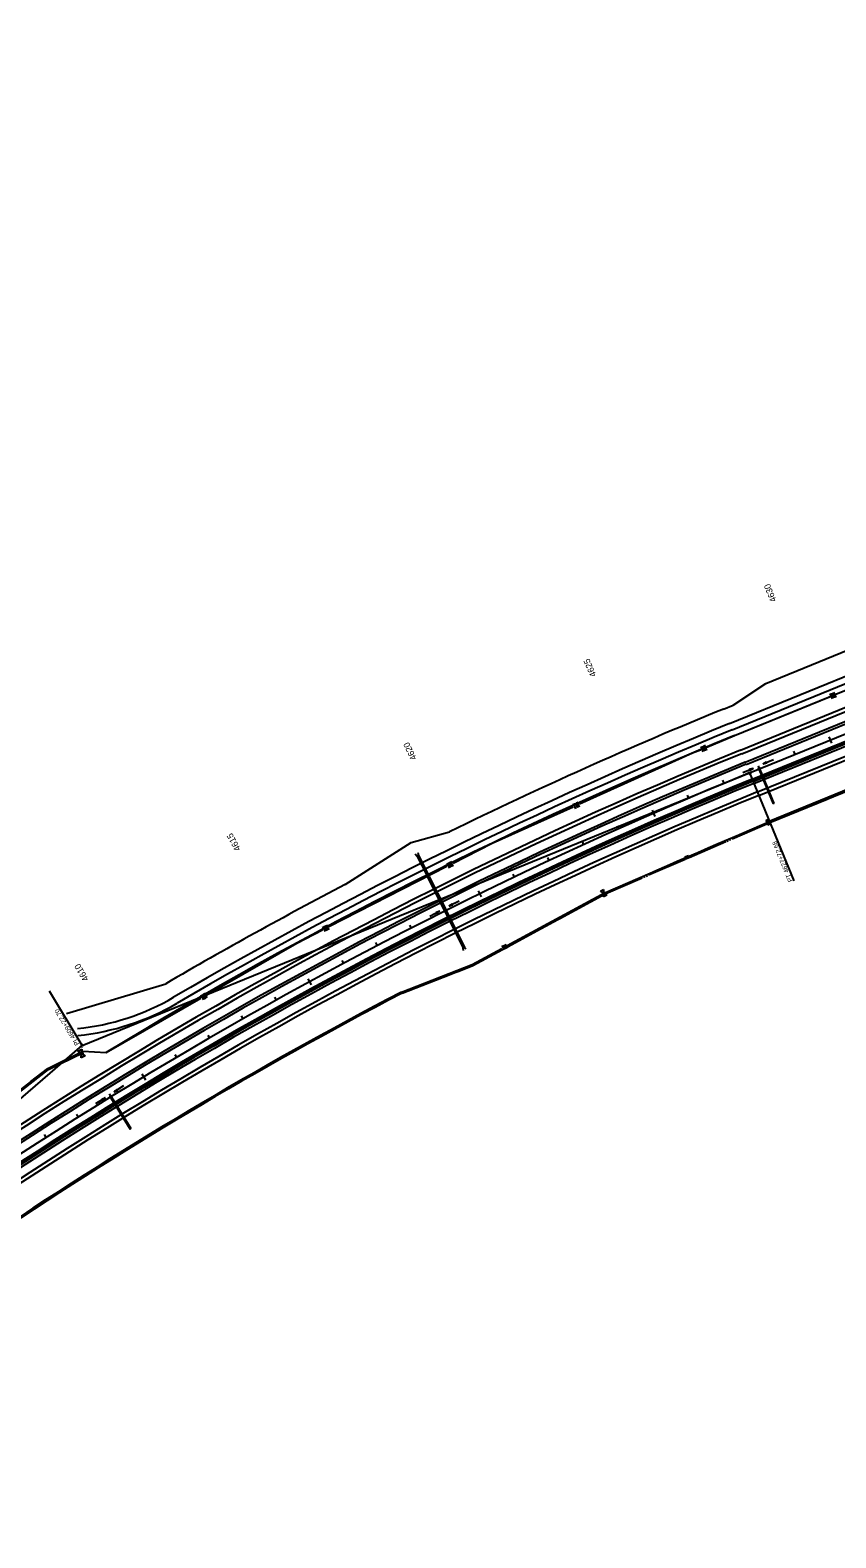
# Model space of a CAD drawing. Extents: x 192699 to 285914, y 194342 to 233219.
# Drawn here: x 208803 to 210907, y 206452 to 210390 of the extents above; entities that cross this region are included whole.
import ezdxf

# ---------------------------------------------------------------- set-up
doc = ezdxf.new("R2010")
doc.units = 0
for name, color, linetype in [('CENT LINE', 7, 'Continuous'), ('CONCRETE', 7, 'Continuous'), ('CURVE DATA', 7, 'Continuous'), ('CURVE LINE', 7, 'Continuous'), ('DRAINAGE', 7, 'Continuous'), ('DRAINAGE ARROWS', 7, 'Continuous'), ('R-W - CofA', 7, 'Continuous'), ('R_Water Annot', 7, 'Continuous'), ('ROAD', 7, 'Continuous'), ('SHOULDER', 7, 'Continuous'), ('STATIONING1', 7, 'Continuous'), ('TEXT', 7, 'Continuous'), ('WRSF', 7, 'Continuous')]:
    doc.layers.add(name, color=color, linetype=linetype)

msp = doc.modelspace()

# ---------------------------------------------------------------- linework, layer by layer
at = {"layer": 'CENT LINE'}
msp.add_line((210682, 208450.3), (219872.3, 212203.9), dxfattribs=at)
msp.add_arc((215014.8, 197841.9), 11459.2, 112.21667, 130.88334, dxfattribs=at)
at = {"layer": 'CONCRETE'}
for p, q in [((210688.8, 208433.7), (214398.6, 209948.9)), ((210690.3, 208430), (214400.2, 209945.2))]:
    msp.add_line(p, q, dxfattribs=at)
for radius in [11441.2, 11437.2]:
    msp.add_arc((215014.8, 197841.9), radius, 112.21667, 130.00508, dxfattribs=at)
at = {"layer": 'CURVE LINE'}
for p, q in [((208938.5, 207738.2), (210682, 208450.3)), ((207514.6, 206505.5), (208938.5, 207738.2))]:
    msp.add_line(p, q, dxfattribs=at)
at = {"layer": 'DRAINAGE'}
for p, q in [((210707.1, 208458.4), (210743.4, 208369.6)), ((210709, 208459.2), (210745.3, 208370.3)), ((209816.8, 208235.7), (209843.1, 208183)), ((209813.2, 208233.9), (209839.6, 208181.2)), ((209841.7, 208176.9), (209884.6, 208091.2)), ((209845.3, 208178.7), (209888.2, 208093)), ((209886.7, 208086.9), (209934, 207992.4)), ((209890.3, 208088.7), (209937.6, 207994.2))]:
    msp.add_line(p, q, dxfattribs=at)
for points in [[(210706.2, 208458), (210709.9, 208459.6), (210708.4, 208463.3), (210704.7, 208461.7)], [(209841.4, 208176.7), (209845.6, 208178.9), (209843.5, 208183.2), (209839.2, 208181)], [(209886.4, 208086.7), (209890.7, 208088.9), (209888.5, 208093.1), (209884.2, 208091)], [(209013.1, 207601.3), (209016.5, 207603.4), (209014.5, 207606.8), (209011, 207604.7)]]:
    msp.add_lwpolyline(points, close=True, dxfattribs=at)
for points in [[(210745.3, 208370.3), (210743.4, 208369.6)], [(209808.7, 208238.4), (209813.2, 208233.9)], [(209816.8, 208235.7), (209813.2, 208233.9)], [(209815.9, 208241.9), (209816.8, 208235.7)], [(209934, 207992.4), (209937.6, 207994.2)], [(209934.9, 207986.2), (209934, 207992.4)], [(209942, 207989.8), (209937.6, 207994.2)], [(209014, 207601.8), (209064.3, 207520)], [(209015.7, 207602.9), (209066, 207521.1)], [(209064.3, 207520), (209066, 207521.1)]]:
    msp.add_lwpolyline(points, dxfattribs=at)
at = {"layer": 'DRAINAGE ARROWS'}
for p, q in [((210725.5, 208478), (210716.8, 208472.8)), ((210726.7, 208475.3), (210716.8, 208472.8)), ((210725.6, 208477.8), (210718.4, 208473.5)), ((210726.6, 208475.5), (210718.4, 208473.5)), ((210725.7, 208477.6), (210720, 208474.1)), ((210726.5, 208475.7), (210720, 208474.1)), ((210725.8, 208477.3), (210721.5, 208474.8)), ((210726.4, 208476), (210721.5, 208474.8)), ((210725.9, 208477.1), (210723.1, 208475.4)), ((210726.3, 208476.2), (210723.1, 208475.4)), ((210726, 208476.9), (210724.6, 208476)), ((210726.2, 208476.4), (210724.6, 208476)), ((210726.7, 208475.3), (210725.5, 208478)), ((210682.6, 208460.5), (210692.5, 208462.9)), ((210683.8, 208457.7), (210682.6, 208460.5)), ((210682.7, 208460.3), (210690.9, 208462.3)), ((210682.8, 208460), (210689.3, 208461.6)), ((210682.9, 208459.8), (210687.8, 208461)), ((210683, 208459.6), (210686.2, 208460.3)), ((210683.1, 208459.3), (210684.7, 208459.7)), ((210683.3, 208458.9), (210684.7, 208459.7)), ((210683.4, 208458.7), (210686.2, 208460.3)), ((210683.5, 208458.4), (210687.8, 208461)), ((210683.6, 208458.2), (210689.3, 208461.6)), ((210683.7, 208458), (210690.9, 208462.3)), ((210683.8, 208457.7), (210692.5, 208462.9)), ((209863.5, 208086.5), (209873.1, 208089.7)), ((209864.9, 208083.8), (209863.5, 208086.5)), ((209863.6, 208086.3), (209871.6, 208089)), ((209863.7, 208086.1), (209870.1, 208088.2)), ((209863.8, 208085.8), (209868.6, 208087.4)), ((209864, 208085.6), (209867.1, 208086.7)), ((209864.1, 208085.4), (209865.6, 208085.9)), ((209864.3, 208085), (209865.6, 208085.9)), ((209864.4, 208084.8), (209867.1, 208086.7)), ((209864.5, 208084.5), (209868.6, 208087.4)), ((209864.6, 208084.3), (209870.1, 208088.2)), ((209864.7, 208084.1), (209871.6, 208089)), ((209864.9, 208083.8), (209873.1, 208089.7)), ((209904.7, 208107.6), (209896.5, 208101.7)), ((209906.1, 208105), (209896.5, 208101.7)), ((209904.8, 208107.4), (209898, 208102.5)), ((209906, 208105.2), (209898, 208102.5)), ((209904.9, 208107.2), (209899.5, 208103.3)), ((209905.9, 208105.4), (209899.5, 208103.3)), ((209905.1, 208107), (209901, 208104)), ((209905.7, 208105.6), (209901, 208104)), ((209905.2, 208106.7), (209902.5, 208104.8)), ((209905.6, 208105.9), (209902.5, 208104.8)), ((209905.3, 208106.5), (209904, 208105.6)), ((209905.5, 208106.1), (209904, 208105.6)), ((209906.1, 208105), (209904.7, 208107.6)), ((209029.1, 207623.4), (209021.5, 207616.7)), ((209030.7, 207620.9), (209021.5, 207616.7)), ((209029.2, 207623.2), (209022.9, 207617.6)), ((209030.6, 207621.1), (209022.9, 207617.6)), ((209029.4, 207623), (209024.4, 207618.6)), ((209030.5, 207621.3), (209024.4, 207618.6)), ((209029.5, 207622.8), (209025.8, 207619.5)), ((209030.3, 207621.5), (209025.8, 207619.5)), ((209029.6, 207622.6), (209027.2, 207620.4)), ((209030.2, 207621.8), (209027.2, 207620.4)), ((209029.8, 207622.4), (209028.6, 207621.3)), ((209030, 207622), (209028.6, 207621.3)), ((209030.7, 207620.9), (209029.1, 207623.4)), ((208990.1, 207598.4), (208999.4, 207602.5)), ((208991.8, 207595.9), (208990.1, 207598.4)), ((208990.3, 207598.2), (208998, 207601.6)), ((208990.4, 207598), (208996.5, 207600.7)), ((208990.5, 207597.8), (208995.1, 207599.8)), ((208990.7, 207597.5), (208993.7, 207598.9)), ((208990.8, 207597.3), (208992.3, 207598)), ((208991.1, 207596.9), (208992.3, 207598)), ((208991.2, 207596.7), (208993.7, 207598.9)), ((208991.3, 207596.5), (208995.1, 207599.8)), ((208991.5, 207596.3), (208996.5, 207600.7)), ((208991.6, 207596.1), (208998, 207601.6)), ((208991.8, 207595.9), (208999.4, 207602.5))]:
    msp.add_line(p, q, dxfattribs=at)
at = {"layer": 'R-W - CofA'}
for p, q in [((210642.3, 208547.5), (212897.4, 209468.6)), ((210891.7, 208657.6), (210897.4, 208643.5)), ((210896.4, 208659.5), (210902.1, 208645.4)), ((210901, 208661.4), (210906.8, 208647.4)), ((210554.4, 208519.3), (210560.1, 208505.3)), ((210559, 208521.2), (210564.8, 208507.2)), ((210563.7, 208523.1), (210569.5, 208509.1)), ((210221.4, 208370.3), (210227.6, 208356.5)), ((210226, 208372.4), (210232.2, 208358.6)), ((210230.6, 208374.5), (210236.8, 208360.7)), ((210724.1, 208326.2), (210731.2, 208329.3)), ((210730.4, 208321.6), (210724.1, 208326.2)), ((210729.5, 208313.9), (210730.4, 208321.6)), ((210736.6, 208317), (210729.5, 208313.9)), ((210731.2, 208329.3), (210730.4, 208321.6)), ((210730.4, 208321.6), (210736.6, 208317)), ((209891.4, 208214.8), (209898.3, 208201.3)), ((209895.9, 208217.1), (209902.8, 208203.6)), ((209900.4, 208219.4), (209907.2, 208205.9)), ((210512.9, 208232.9), (210516.8, 208223.8)), ((210515.9, 208234.2), (210519.8, 208225.1)), ((210518.9, 208235.5), (210522.9, 208226.4)), ((210292.2, 208141), (210300.8, 208145.7)), ((210300.6, 208135.9), (210292.2, 208141)), ((210300.3, 208126.1), (210300.6, 208135.9)), ((210308.9, 208130.8), (210300.3, 208126.1)), ((210300.8, 208145.7), (210300.6, 208135.9)), ((210300.6, 208135.9), (210308.9, 208130.8)), ((209566.8, 208048.9), (209573.6, 208035.5)), ((209571.3, 208051.2), (209578.1, 208037.7)), ((209575.7, 208053.5), (209582.6, 208040)), ((210038.8, 208001), (210044.8, 207990)), ((210042.5, 208003), (210048.5, 207992)), ((210035.2, 207999.1), (210041.1, 207988)), ((209248.5, 207870.5), (209256.1, 207857.3)), ((209252.9, 207873), (209260.5, 207859.9)), ((209257.3, 207875.5), (209264.8, 207862.4)), ((208927.7, 207723.7), (208937.8, 207728.7)), ((208937.8, 207728.7), (208937.1, 207717.3)), ((208937.1, 207717.3), (208927.7, 207723.7)), ((208936.3, 207706), (208937.1, 207717.3)), ((208946.5, 207711), (208936.3, 207706)), ((208937.1, 207717.3), (208946.5, 207711)), ((208940.5, 207723.3), (209001.9, 207719.8))]:
    msp.add_line(p, q, dxfattribs=at)
for points in [[(210735, 208320.7), (215389, 210221.6), (215624.3, 210306.9), (215851.9, 210410.7), (216685.1, 210751), (217161.2, 210907.6), (217425.7, 211053.4), (218805.1, 211616.8)], [(210614, 208617), (210639.2, 208627.3), (210724.3, 208683.6), (211927.8, 209175.2), (212109.1, 209260), (212398.2, 209345.7), (212715.2, 209475.2), (212818.4, 209612.9)], [(210570.3, 208517.7), (210642.3, 208547.5), (210642.3, 208547.5), (210890.8, 208649)], [(210570.3, 208517.7), (210570.3, 208517.7)], [(210237.4, 208369.2), (210533, 208502.2), (210553.5, 208510.7)], [(210733.4, 208324.5), (211058.5, 208457.3)], [(209907.4, 208214.5), (210009.9, 208266.9), (210220.8, 208361.8)], [(210237.4, 208369.2), (210237.4, 208369.2)], [(210735, 208320.7), (210884.5, 208381.8)], [(210889.3, 208383.8), (210895.1, 208386.1)], [(210899.9, 208388.1), (210905.7, 208390.4)], [(210523.3, 208232), (210733.9, 208323.1)], [(210636.1, 208278), (210735, 208320.7)], [(209626.1, 208158.4), (209798, 208268.8), (209898, 208296)], [(210629.4, 208275), (210633.1, 208276.6)], [(210524.4, 208229.6), (210619.6, 208270.8)], [(210622.7, 208272.1), (210626.3, 208273.7)], [(209582.8, 208048.6), (209891.2, 208206.2)], [(209907.4, 208214.5), (209907.4, 208214.5)], [(210305.4, 208137.7), (210512.5, 208227.3)], [(210418.3, 208183.7), (210513.5, 208224.9)], [(210306.5, 208135.3), (210401.7, 208176.5)], [(210404.8, 208177.9), (210408.5, 208179.4)], [(210411.5, 208180.8), (210415.2, 208182.4)], [(209774.2, 207874.8), (209959.1, 207946.8), (210306.5, 208135.3)], [(210048.4, 207999.1), (210304.9, 208138.2)], [(210186.2, 208070), (210306.5, 208135.3)], [(209264.6, 207870.9), (209499.1, 208005.8), (209566.6, 208040.4)], [(209582.8, 208048.6), (209582.8, 208048.6)], [(210050, 207996.2), (210166, 208059.1)], [(210169.7, 208061.1), (210174.2, 208063.6)], [(210177.9, 208065.6), (210182.4, 208068)], [(209773, 207877.9), (209957.6, 207949.9), (210035.2, 207991.9)], [(209918.5, 207931), (209959.1, 207946.8), (210036.8, 207989)], [(209774.2, 207874.8), (209897.2, 207922.7)], [(209901.1, 207924.3), (209905.9, 207926.1)], [(209909.8, 207927.6), (209914.6, 207929.5)], [(208898.2, 207821.7), (209157.1, 207899.6)], [(208940.5, 207723.3), (209001.9, 207719.8), (209248.8, 207861.9)], [(209264.6, 207870.9), (209264.6, 207870.9)], [(208661.5, 207537.2), (208771.2, 207612.7), (208851.2, 207675.1), (208942.2, 207719.9)], [(208769, 207615.8), (208849.2, 207678.4), (208940.5, 207723.3)], [(208804.9, 207643.9), (208849.2, 207678.4), (208940.5, 207723.3)]]:
    msp.add_lwpolyline(points, dxfattribs=at)
for radius, start, end in [(11639.2, 112.21667, 116.08006), (11564.2, 112.21667, 121.33007), (11319.2, 112.21667, 114.58007), (11639.2, 117.58006, 120.21724), (11322.5, 117.58007, 130.49311), (11319.2, 117.58007, 130.47508), (11319.2, 117.58007, 130.47508)]:
    msp.add_arc((215014.8, 197841.9), radius, start, end, dxfattribs=at)
at = {"layer": 'R_Water Annot'}
for p, q in [((210744.6, 208484.2), (210716.8, 208472.8)), ((210725.5, 208478), (210716.8, 208472.8)), ((210726.7, 208475.3), (210716.8, 208472.8)), ((210725.6, 208477.8), (210718.4, 208473.5)), ((210726.6, 208475.5), (210718.4, 208473.5)), ((210725.7, 208477.6), (210720, 208474.1)), ((210726.5, 208475.7), (210720, 208474.1)), ((210725.8, 208477.3), (210721.5, 208474.8)), ((210726.4, 208476), (210721.5, 208474.8)), ((210725.9, 208477.1), (210723.1, 208475.4)), ((210726.3, 208476.2), (210723.1, 208475.4)), ((210726, 208476.9), (210724.6, 208476)), ((210726.2, 208476.4), (210724.6, 208476)), ((210726.7, 208475.3), (210725.5, 208478)), ((210664.7, 208451.6), (210692.5, 208462.9)), ((210682.6, 208460.5), (210692.5, 208462.9)), ((210683.8, 208457.7), (210682.6, 208460.5)), ((210682.7, 208460.3), (210690.9, 208462.3)), ((210682.8, 208460), (210689.3, 208461.6)), ((210682.9, 208459.8), (210687.8, 208461)), ((210683, 208459.6), (210686.2, 208460.3)), ((210683.1, 208459.3), (210684.7, 208459.7)), ((210683.3, 208458.9), (210684.7, 208459.7)), ((210683.4, 208458.7), (210686.2, 208460.3)), ((210683.5, 208458.4), (210687.8, 208461)), ((210683.6, 208458.2), (210689.3, 208461.6)), ((210683.7, 208458), (210690.9, 208462.3)), ((210683.8, 208457.7), (210692.5, 208462.9)), ((209846.4, 208076.1), (209873.1, 208089.7)), ((209863.5, 208086.5), (209873.1, 208089.7)), ((209864.9, 208083.8), (209863.5, 208086.5)), ((209863.6, 208086.3), (209871.6, 208089)), ((209863.7, 208086.1), (209870.1, 208088.2)), ((209863.8, 208085.8), (209868.6, 208087.4)), ((209864, 208085.6), (209867.1, 208086.7)), ((209864.1, 208085.4), (209865.6, 208085.9)), ((209864.3, 208085), (209865.6, 208085.9)), ((209864.4, 208084.8), (209867.1, 208086.7)), ((209864.5, 208084.5), (209868.6, 208087.4)), ((209864.6, 208084.3), (209870.1, 208088.2)), ((209864.7, 208084.1), (209871.6, 208089)), ((209864.9, 208083.8), (209873.1, 208089.7)), ((209923.2, 208115.5), (209896.5, 208101.7)), ((209904.7, 208107.6), (209896.5, 208101.7)), ((209906.1, 208105), (209896.5, 208101.7)), ((209904.8, 208107.4), (209898, 208102.5)), ((209906, 208105.2), (209898, 208102.5)), ((209904.9, 208107.2), (209899.5, 208103.3)), ((209905.9, 208105.4), (209899.5, 208103.3)), ((209905.1, 208107), (209901, 208104)), ((209905.7, 208105.6), (209901, 208104)), ((209905.2, 208106.7), (209902.5, 208104.8)), ((209905.6, 208105.9), (209902.5, 208104.8)), ((209905.3, 208106.5), (209904, 208105.6)), ((209905.5, 208106.1), (209904, 208105.6)), ((209906.1, 208105), (209904.7, 208107.6)), ((209046.7, 207633), (209021.5, 207616.7)), ((209029.1, 207623.4), (209021.5, 207616.7)), ((209030.7, 207620.9), (209021.5, 207616.7)), ((209029.2, 207623.2), (209022.9, 207617.6)), ((209030.6, 207621.1), (209022.9, 207617.6)), ((209029.4, 207623), (209024.4, 207618.6)), ((209030.5, 207621.3), (209024.4, 207618.6)), ((209029.5, 207622.8), (209025.8, 207619.5)), ((209030.3, 207621.5), (209025.8, 207619.5)), ((209029.6, 207622.6), (209027.2, 207620.4)), ((209030.2, 207621.8), (209027.2, 207620.4)), ((209029.8, 207622.4), (209028.6, 207621.3)), ((209030, 207622), (209028.6, 207621.3)), ((209030.7, 207620.9), (209029.1, 207623.4)), ((208974.1, 207586.3), (208999.4, 207602.5)), ((208990.1, 207598.4), (208999.4, 207602.5)), ((208991.8, 207595.9), (208990.1, 207598.4)), ((208990.3, 207598.2), (208998, 207601.6)), ((208990.4, 207598), (208996.5, 207600.7)), ((208990.5, 207597.8), (208995.1, 207599.8)), ((208990.7, 207597.5), (208993.7, 207598.9)), ((208990.8, 207597.3), (208992.3, 207598)), ((208991.1, 207596.9), (208992.3, 207598)), ((208991.2, 207596.7), (208993.7, 207598.9)), ((208991.3, 207596.5), (208995.1, 207599.8)), ((208991.5, 207596.3), (208996.5, 207600.7)), ((208991.6, 207596.1), (208998, 207601.6)), ((208991.8, 207595.9), (208999.4, 207602.5))]:
    msp.add_line(p, q, dxfattribs=at)
at = {"layer": 'ROAD'}
for p, q in [((210661.6, 208500.3), (229316.5, 216119.6)), ((210670.7, 208478.1), (229325.6, 216097.4)), ((210702.4, 208400.3), (229357.4, 216019.6)), ((210693.4, 208422.5), (219316.1, 211944.3)), ((210629.4, 208579), (212730.6, 209437.2)), ((210636.3, 208562.3), (212737.4, 209420.5))]:
    msp.add_line(p, q, dxfattribs=at)
for centre, radius, start, end in [((215014.8, 197841.9), 11598.2, 112.21669, 120.21697), ((215014.8, 197841.9), 11580.2, 112.21669, 120.21697), ((215014.8, 197841.9), 11513.2, 112.21667, 130.88334), ((215014.8, 197841.9), 11489.2, 112.21667, 130.88334), ((215014.8, 197841.9), 11429.2, 112.21667, 130.88334), ((215014.8, 197841.9), 11405.2, 112.21667, 130.88334), ((208861.9, 208406.5), 627.6, 275.9005, 300.217), ((208861.9, 208406.5), 645.6, 275.8547, 300.217)]:
    msp.add_arc(centre, radius, start, end, dxfattribs=at)
at = {"layer": 'SHOULDER'}
for p, q in [((210657.8, 208509.6), (225591.1, 214608.8)), ((210691.1, 208428.1), (225763.2, 214584)), ((210672.9, 208472.5), (225606.2, 214571.8)), ((210706.2, 208391.1), (225778.4, 214547))]:
    msp.add_line(p, q, dxfattribs=at)
for radius in [11523.2, 11483.2, 11435.2, 11395.2]:
    msp.add_arc((215014.8, 197841.9), radius, 112.21667, 130.88334, dxfattribs=at)
at = {"layer": 'STATIONING1'}
for points in [[(210889.1, 208544.6), (210895.9, 208527.9)], [(210796.5, 208506.8), (210799.9, 208498.5)], [(210703.9, 208469), (210707.3, 208460.7)], [(210611.4, 208430.9), (210614.8, 208422.6)], [(210519.1, 208392.1), (210522.7, 208383.8)], [(210427.2, 208352.5), (210434.4, 208336)], [(210335.7, 208312), (210339.4, 208303.8)], [(210244.5, 208270.8), (210248.2, 208262.6)], [(210153.7, 208228.8), (210157.5, 208220.6)], [(210063.2, 208186), (210067.1, 208177.8)], [(209973.1, 208142.4), (209981, 208126.2)], [(209883.4, 208098), (209887.5, 208089.9)], [(209794.1, 208052.8), (209798.2, 208044.8)], [(209705.2, 208006.9), (209709.4, 207998.9)], [(209616.7, 207960.1), (209621, 207952.2)], [(209528.6, 207912.6), (209537.2, 207896.8)], [(209441, 207864.4), (209445.3, 207856.5)], [(209353.7, 207815.4), (209358.1, 207807.5)], [(209266.9, 207765.6), (209271.4, 207757.8)], [(209180.5, 207715), (209185.1, 207707.3)], [(209094.6, 207663.8), (209103.9, 207648.3)], [(209009.1, 207611.7), (209013.8, 207604)], [(208924.1, 207558.9), (208928.8, 207551.3)], [(208839.5, 207505.4), (208844.3, 207497.8)]]:
    msp.add_lwpolyline(points, dxfattribs=at)
at = {"layer": 'TEXT'}
for points in [[(210682, 208450.3), (210797.2, 208168.4)], [(208938.5, 207738.2), (208853.6, 207879.9)]]:
    msp.add_lwpolyline(points, dxfattribs=at)
at = {"layer": 'WRSF'}
msp.add_line((210689.6, 208431.8), (214399.4, 209947), dxfattribs=at)
msp.add_arc((215014.8, 197841.9), 11439.2, 112.21667, 130.00508, dxfattribs=at)

# ---------------------------------------------------------------- texts
at = {"layer": 'CURVE DATA'}
for s, rotation, p in [('C', 22.2167, (210679, 208443.2)), ('B', 359.7165, (208933, 207732.8))]:
    msp.add_text(s, height=10.8, rotation=rotation, dxfattribs=at).set_placement(p)
at = {"layer": 'STATIONING1'}
for s, rotation, p in [('4630', 112.2167, (210752.7, 208900.2)), ('4625', 113.5801, (210282.2, 208705.3)), ('4620', 116.0801, (209813.1, 208488)), ('4615', 118.5801, (209353.4, 208251.5)), ('4610', 121.0801, (208956.8, 207911.6))]:
    msp.add_text(s, height=16.5, rotation=rotation, dxfattribs=at).set_placement(p)
at = {"layer": 'TEXT'}
for s, rotation, p in [('PT 4627+72.68', 112.2167, (210794.7, 208168)), ('PI 4609+22.70', 120.921, (208931.8, 207742.4))]:
    msp.add_text(s, height=12, rotation=rotation, dxfattribs=at).set_placement(p)

doc.saveas('drawing.dxf')
